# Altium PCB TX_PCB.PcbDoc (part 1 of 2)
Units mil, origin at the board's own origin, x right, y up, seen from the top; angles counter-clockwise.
Board outline 1955 x 2115 mil, 2 copper layers (Top Layer, Bottom Layer); 123 components, 95 nets, 485 pads, 266 vias.
Unrouted connection lines stored in the file: 109.
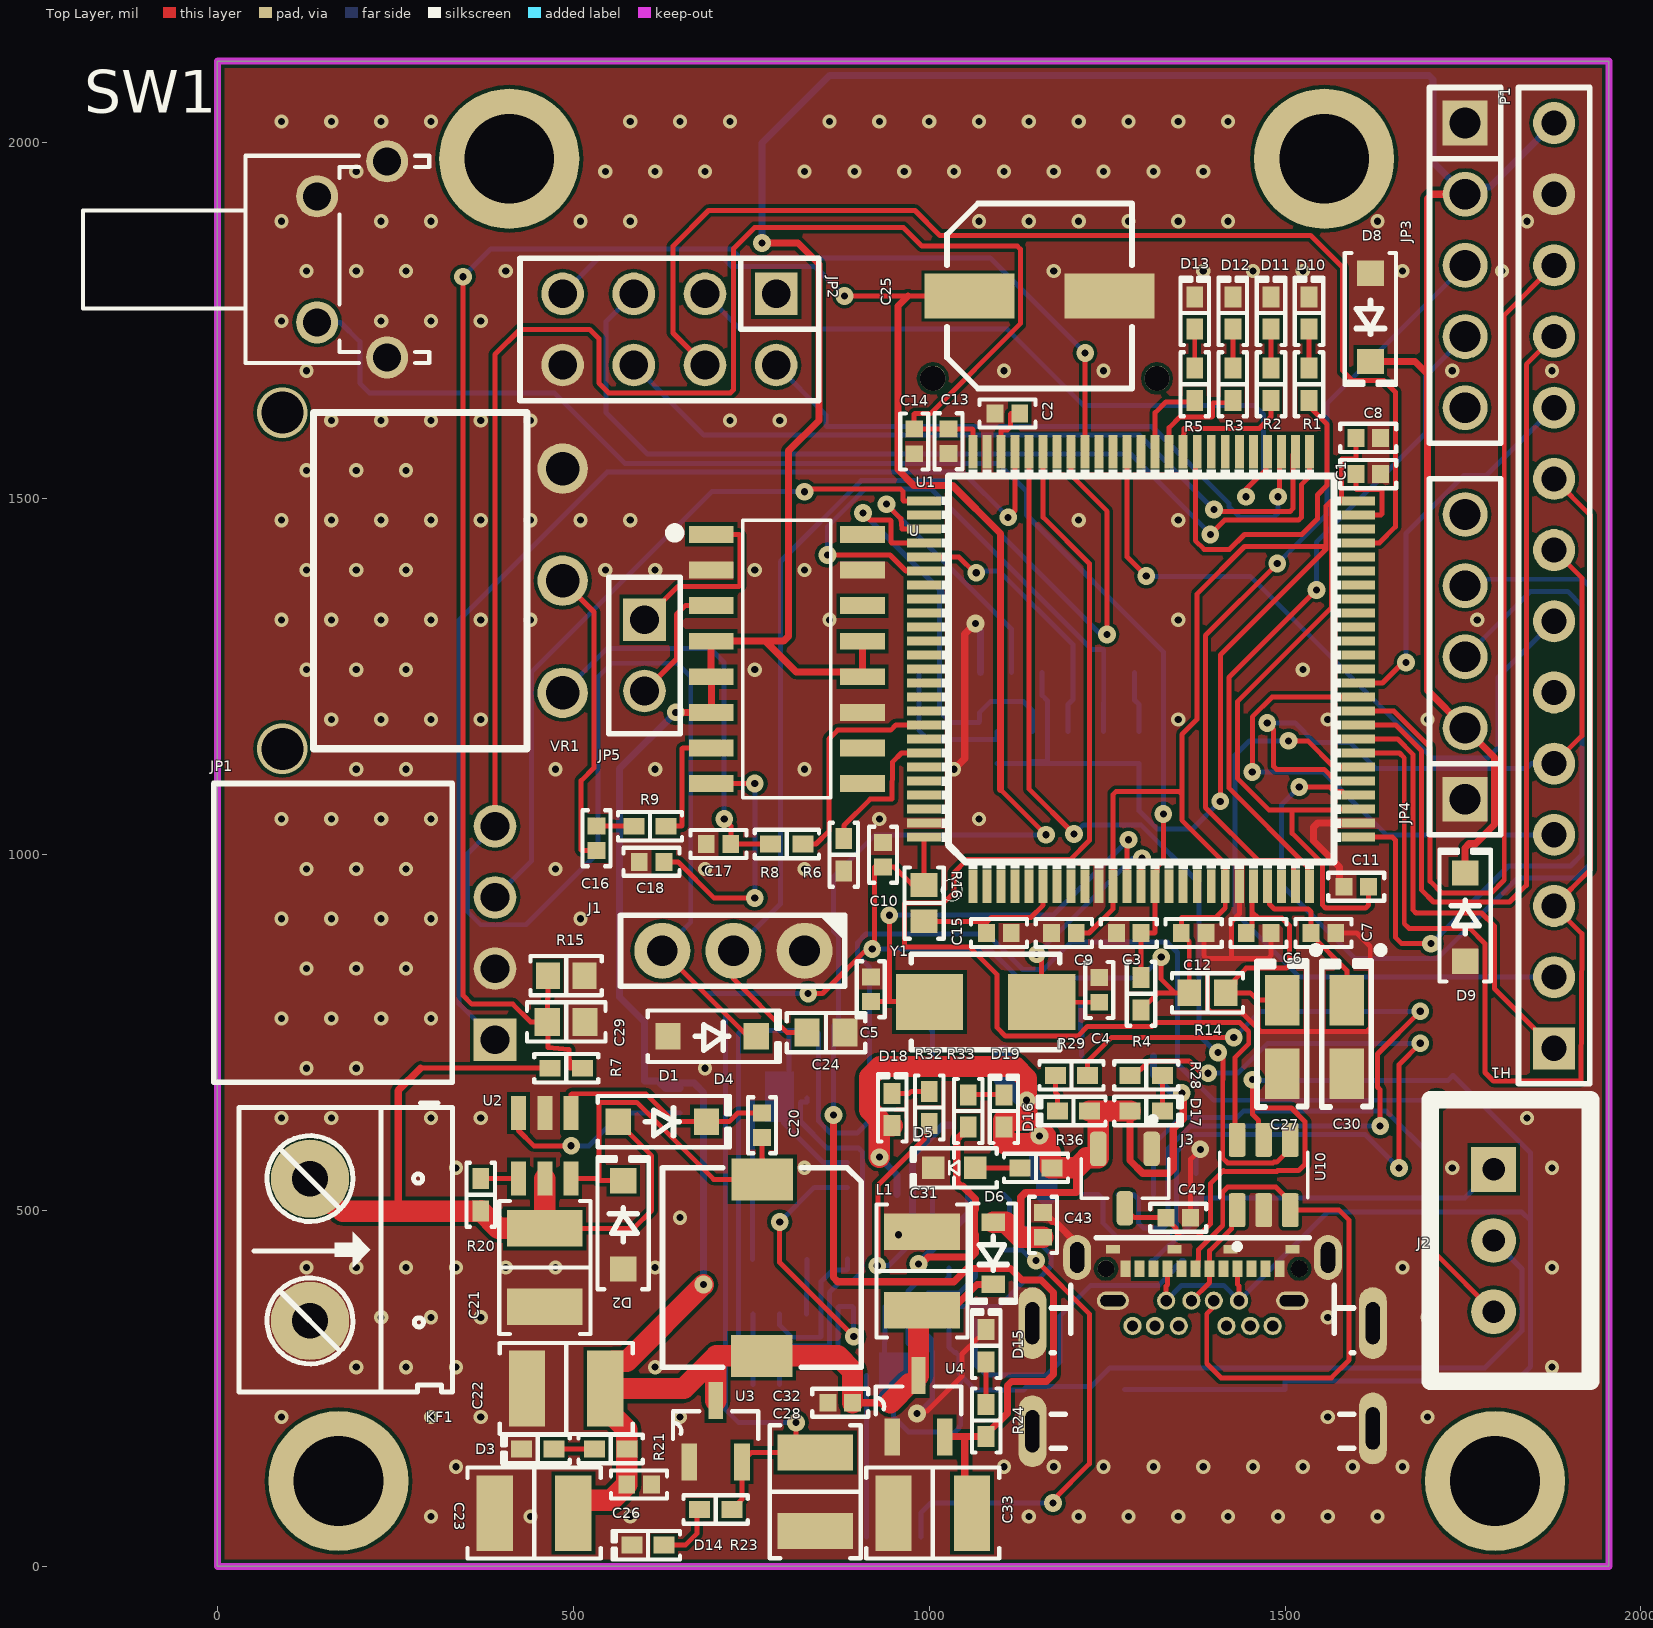
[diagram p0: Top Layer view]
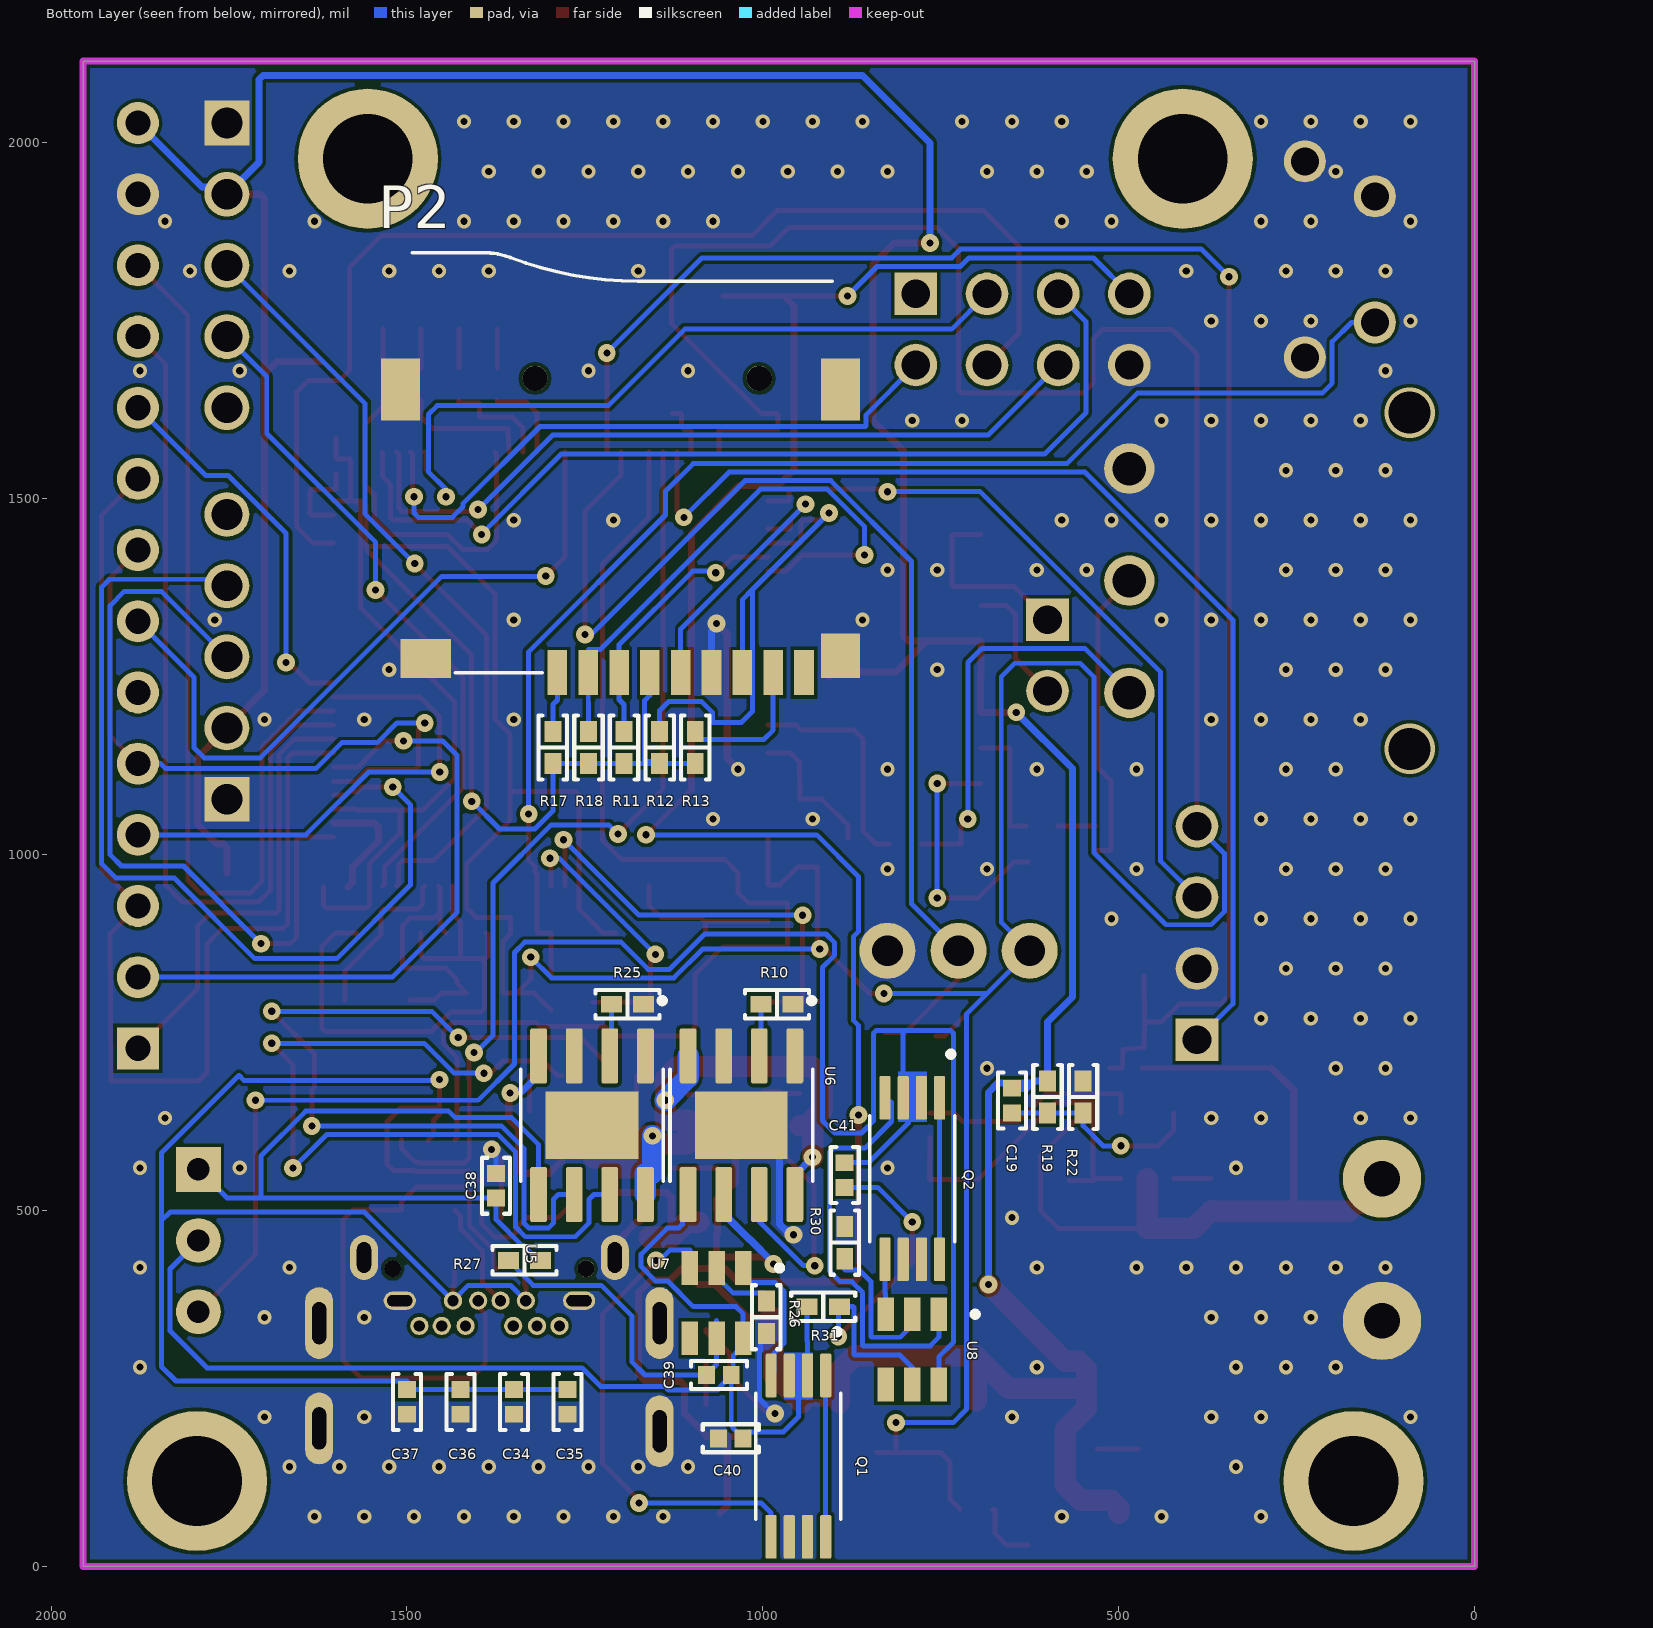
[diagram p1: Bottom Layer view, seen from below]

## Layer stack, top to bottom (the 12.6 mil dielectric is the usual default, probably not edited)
Top Solder: solder mask 0.4, Solder Resist, Dk 3.5
Top Layer: signal copper 1.4
Dielectric 1: dielectric 12.6, FR-4, Dk 4.8
Bottom Layer: signal copper 1.4
Bottom Solder: solder mask 0.4, Solder Resist, Dk 3.5

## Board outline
0,0 0,2115 1955,2115 1955,0

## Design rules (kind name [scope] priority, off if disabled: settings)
Clearance [All] p1: gap=5 ignorepadtopadclearanceinfootprint=FALSE
PolygonConnect PolygonConnect_5 [All vs IsNamedPolygon('GND_L02_P001')] p1: connectstyle=Direct reliefconductorwidth=10 reliefentries=4 polygonreliefangle="90 Angle" airgapwidth=10
PolygonConnect PolygonConnect_4 [All vs IsNamedPolygon('GND_L01_P000')] p2: connectstyle=Direct reliefconductorwidth=10 reliefentries=4 polygonreliefangle="90 Angle" airgapwidth=10
PolygonConnect PolygonConnect_3 [All vs IsNamedPolygon('GND_L01_P000')] p3: connectstyle=Direct reliefconductorwidth=10 reliefentries=4 polygonreliefangle="90 Angle" airgapwidth=10
PolygonConnect PolygonConnect_2 [All vs IsNamedPolygon('GND_L02_P001')] p4: connectstyle=Direct reliefconductorwidth=10 reliefentries=4 polygonreliefangle="90 Angle" airgapwidth=10
PolygonConnect PolygonConnect_1 [All vs IsNamedPolygon('GND_L01_P000')] p5: connectstyle=Direct reliefconductorwidth=10 reliefentries=4 polygonreliefangle="90 Angle" airgapwidth=10
PolygonConnect [All] p6: connectstyle=Relief reliefconductorwidth=10 reliefentries=4 polygonreliefangle="90 Angle" airgapwidth=10
RoutingVias [All] p1: holewidth=10 width=25 viastyle="Through Hole" minholewidth=10 minwidth=20 maxholewidth=28 maxwidth=50
SolderMaskExpansion [All] p1: expansion=4 istentingtop=FALSE
Width [All] p1: maxlimit=40 minlimit=7 preferedwidth=30 minimp=50.000000 maximp=50.000000 favimp=50.000000
30 further rules are at their usual default settings.

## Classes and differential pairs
component class USB_C: C34 C35 C36 C37 C38 C39 C40 C41 C42 C43 D5 D16 D17 D18 D19 H1 J2 J3 Q1 Q2 R10 R25 R26 R27 R28 R29 R30 R31 R32 R33 R36 U5 U6 U7 U8 U10
component class Audio: C16 C17 C18 JP5 P2 R8 R9 R11 R12 R13 R17 R18 U VR1
component class Power_2: C19 C20 C21 C22 C23 C26 C28 C31 C32 C33 D1 D2 D3 D14 D15 KF1 L1 R19 R20 R21 R22 R23 R24 U2 U3 U4
component class MAIN_TX: C1 C2 C3 C4 C5 C6 C7 C8 C9 C10 C11 C12 C13 C14 C15 C24 C25 C27 C29 C30 D4 D8 D9 D10 D11 D12 D13 J1 JP1 JP2 JP3 JP4 P1 R2 R3 R4 R5 R6 R7 R14 R15 R16 SW1 U1 Y1

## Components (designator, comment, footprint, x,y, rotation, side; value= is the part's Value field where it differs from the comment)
C1 "2.2 µF" "CAP 0402_1005" 1617,1534.69 r180 top
C2 "2.2 µF" "CAP 0402_1005" 1110,1620 r0 top
C3 "0.1 µF" "CAP 0402_1005" 1280.4,890 r0 top
C4 "20 pF" "CAP 0402_1005" 1239,810 r270 top
C5 "20 pF" "CAP 0402_1005" 918,811 r270 top
C6 "0.1 µF" "CAP 0402_1005" 1462.8,890 r180 top
C7 "0.1 µF" "CAP 0402_1005" 1554,890 r0 top
C8 "0.1 µF" "CAP 0402_1005" 1617,1585.69 r180 top
C9 "0.1 µF" "CAP 0402_1005" 1189.2,890 r0 top
C10 "0.1 µF" "CAP 0402_1005" 935,1000 r270 top
C11 "0.1 µF" "CAP 0402_1005" 1600,955 r0 top
C12 "0.1 µF" "CAP 0402_1005" 1371.6,890 r180 top
C13 "0.1 µF" "CAP 0402_1005" 1027,1581 r90 top
C14 "0.1 µF" "CAP 0402_1005" 979,1580.68 r90 top
C15 "1 µF" "CAP 0402_1005" 1098,890 r180 top
C16 "0.22 µF" "CAP 0402_1005" 532.64,1023 r90 top
C17 "0.1 µF" "CAP 0402_1005" 704,1015 r0 top
C18 "1 µF" "CAP 0402_1005" 610,990 r0 top
C19 "1000 pF" "CAP 0402_1005" 650,654.56 r90 bottom
C20 "0.1 µF" "CAP 0402_1005" 765,619.92 r90 top
C21 "10 µF" "CAP 1210_3225 - 1MM" 460,419.92 r90 top
C22 "22 µF" "CAP 1210_3225 - 1MM" 490,249.92 r0 top
C23 "10 µF" "CAP 1210_3225 - 1MM" 445,74.92 r0 top
C24 "0.1 µF" "CAP 0603_1608" 855,750 r180 top
C25 "220 µF" "CAP ALSMD 6.6MM H6.1MM" 1155,1785 r0 top
C26 "0.1µF" "CAP 0402_1005" 592.44,114.92 r180 top
C27 "1µF" "CAP POL 1206_3216" 1496,744 r270 top
C28 "10 µF" "CAP 1210_3225 - 1MM" 840,104.92 r90 top
C29 "0.1 µF" "CAP 0603_1608" 490,765 r180 top
C30 "1µF" "CAP POL 1206_3216" 1587,744 r270 top
C31 "10 µF" "CAP 1210_3225 - 1MM" 990,415 r270 top
C32 "0.1µF" "CAP 0402_1005" 875,229.92 r0 top
C33 "10 µF" "CAP 1210_3225 - 1MM" 1005,74.92 r0 top
C34 "0.1 µF" "CAP 0402_1005" 1349.74,231.1 r270 bottom
C35 "0.1 µF" "CAP 0402_1005" 1274.61,231.1 r270 bottom
C36 "0.1 µF" "CAP 0402_1005" 1424.87,231.1 r270 bottom
C37 "0.1 µF" "CAP 0402_1005" 1500,231.1 r270 bottom
C38 "10 µF" "CAP 0402_1005" 1375,534.92 r90 bottom
C39 "0.1 µF" "CAP 0402_1005" 1061.68,269 r180 bottom
C40 "10 µF" "CAP 0402_1005" 1045,180 r0 bottom
C41 "0.1 µF" "CAP 0402_1005" 885,549.92 r90 bottom
C42 "1 µF" "CAP 0402_1005" 1350,489.92 r180 top
C43 "1 µF" "CAP 0402_1005" 1160,479.92 r90 top
D1 "1N5819HW-7-F" SOD-123 625,624.92 r0 top
D2 "1N5819HW-7-F" SOD-123 570,479.92 r90 top
D3 "Green" "LED 0402_1005 GREEN" 450,164.92 r180 top
D4 "1N5819HW-7-F" SOD-123 695,745 r0 top
D5 "Blue" "LED 0603_1608 BLUE" 1035,559.92 r180 top
D6 "BAT60JFILM" SOD323 1090,439.92 r270 top
D8 "1N5819HW-7-F" SOD-123 1620,1755 r270 top
D9 "1N5819HW-7-F" SOD-123 1753,912.29 r90 top
D10 "Red" "LED 0402_1005 RED" 1533.72,1761 r90 top
D11 "Yellow" "LED 0402_1005 YELLOW" 1480.19,1761 r90 top
D12 "Green" "LED 0402_1005 GREEN" 1426.67,1761 r90 top
D13 "Blue" "LED 0402_1005 BLUE" 1373.14,1761 r90 top
D14 "Yellow" "LED 0402_1005 YELLOW" 605,29.92 r180 top
D15 "Red" "LED 0402_1005 RED" 1080,309.92 r90 top
D16 "Green" "LED 0402_1005 GREEN" 1202.64,639.92 r180 top
D17 "Red" "LED 0402_1005 RED" 1305,639.92 r0 top
D18 "Red" "LED 0402_1005 RED" 947.95,641.97 r90 top
D19 "Green" "LED 0402_1005 GREEN" 1105,639.92 r90 top
H1 "Header 3P 2.54 Duc Thang" XH2.54M-3 1793,557.92 r270 top
J1 "M20-7820342" "HARWIN M20-7820345" 725,865 r270 top
J2 "2129691-1" "TE USB-C 2129691-1" 1384.17,241.1 r180 top
J3 "MCP1700T-5002E/TT" SOT95P237X112-3N#1 1275,544.92 r270 top
JP1 "JP 1x4 2.54" "JP 1x4 CC" 390,890 r90 top
JP2 "JP 2x4 2.54" "JP 2x4 CT" 635,1738 r180 top
JP3 "JP 1x5 2.54" "JP 1x5 DT" 1753,2028 r270 top
JP4 "JP 1x5 2.54" "JP 1x5 DT" 1753,1078 r90 top
JP5 "JP 1x2 2.54" "JP 1x2 CT" 600,1330 r270 top
KF1 "CON 2 KF301" "Con 2 KF301 5.08" 130,544.92 r270 top
L1 "10µH" "TDK SLF7032" 765,419.92 r270 top
P1 "Header 14" HDR1X14 1878,728 r90 top
P2 "ST-TF-003A" SUNTECH_ST-TF-003A 1150,1465.72 r0 bottom
Q1 "FS8205A" SOP65P640X120-8N 950,154.92 r270 bottom
Q2 "FS8205A" SOP65P640X120-8N 790,544.92 r270 bottom
R1 "680 Ohms" "RES 0402_1005" 1533.72,1661 r90 top
R2 "680 Ohms" "RES 0402_1005" 1480.19,1661 r90 top
R3 "680 Ohms" "RES 0402_1005" 1426.67,1661 r90 top
R4 "100 kOhms" "RES 0402_1005" 1297.72,804.68 r270 top
R5 "680 Ohms" "RES 0402_1005" 1373.14,1661 r90 top
R6 "10 kOhms" "RES 0402_1005" 880,1000 r90 top
R7 "10 kOhms" "RES 0402_1005" 490,700 r180 top
R8 "4.7 kOhms" "RES 0402_1005" 800,1015 r0 top
R9 "10 kOhms" "RES 0402_1005" 607.64,1040 r0 top
R10 "1.2 kOhms" "RES 0402_1005" 980,789.92 r0 bottom
R11 "4.7 kOhms" "RES 0402_1005" 1195,1150.72 r270 bottom
R12 "4.7 kOhms" "RES 0402_1005" 1145,1150.72 r270 bottom
R13 "4.7 kOhms" "RES 0402_1005" 1095,1150.72 r270 bottom
R14 "47 Ohms" "RES 0603_1608" 1391,806 r0 top
R15 "20 kOhms" "RES 0603_1608" 490,830 r180 top
R16 "0 Ohms" "RES 0603_1608" 992.77,932 r270 top
R17 "4.7 kOhms" "RES 0402_1005" 1295,1150.72 r270 bottom
R18 "4.7 kOhms" "RES 0402_1005" 1245,1150.72 r270 bottom
R19 "52.3 kOhms" "RES 0402_1005" 600,659.56 r90 bottom
R20 "100 kOhms" "RES 0402_1005" 370,522.28 r270 top
R21 "1 kOhms" "RES 0402_1005" 552.48,164.92 r0 top
R22 "10 kOhms" "RES 0402_1005" 550,659.56 r270 bottom
R23 "680 Ohms" "RES 0402_1005" 700,79.92 r0 top
R24 "680 Ohms" "RES 0402_1005" 1080,204.92 r270 top
R25 "1.2 kOhms" "RES 0402_1005" 1190,789.92 r0 bottom
R26 "1 kOhms" "RES 0402_1005" 995,350 r270 bottom
R27 "110 Ohms" "RES 0402_1005" 1335,430 r180 bottom
R28 "1 kOhms" "RES 0402_1005" 1305,689.92 r0 top
R29 "1 kOhms" "RES 0402_1005" 1200,689.92 r0 top
R30 "1 kOhms" "RES 0402_1005" 885,454.92 r90 bottom
R31 "110 Ohms" "RES 0402_1005" 915,364.92 r0 bottom
R32 "1 kOhms" "RES 0402_1005" 1000,644.92 r90 top
R33 "1 kOhms" "RES 0402_1005" 1055,639.92 r270 top
R36 "1 kOhms" "RES 0402_1005" 1150,559.92 r0 top
SW1 "431256083716" 4312560837x6 105.55,1836.42 r270 top
U "PAM8403DR" SOIC127P605X150-16N 800,1275 r0 top
U1 "MCU-STM32F407VET6(LQFP100)" LQFP100-0.5-13.8X13.8MM 1297.89,1260.88 r90 top
U2 "LM2734YMK" SOT95P285X100-6N 460,590.92 r270 top
U3 "MCP1700T-3302E/TT" SOT95P237X112-3N#2 700,189.92 r90 top
U4 "MCP1700T-3302E/TT" SOT95P237X112-3N#2 985,224.92 r90 top
U5 "TP4056" SOP127P600X175-9N 1240,619.92 r270 bottom
U6 "TP4056" SOP127P600X175-9N 1030,619.92 r270 bottom
U7 "DW01A" SOT95P280X145-6N#1 1065,370 r270 bottom
U8 "DW01A" SOT95P280X145-6N#1 790,304.92 r270 bottom
U10 "USBLC6-2SC6" SOT95P280X145-6N#2 1470,549.92 r90 top
VR1 "VR 10Kohm" "VR 10kohm" 485,1148.78 r90 top
Y1 "8 MHz" "NDK NX5032GA" 1079.26,793 r180 top

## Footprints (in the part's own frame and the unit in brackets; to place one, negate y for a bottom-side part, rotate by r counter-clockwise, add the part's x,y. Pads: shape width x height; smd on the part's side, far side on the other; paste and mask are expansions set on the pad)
4312560837x6 [mm] "6x6mm right angle Tact Switch with ground terminal, THT version"
  round 1.5 hole 1: 1(-2.25,0.875) 2(2.25,0.875) G1(-3.5,3.375) G2(3.5,3.375)
  silkscreen extent -3.7,-7.47 3.7,4.87, body extent -4.2,-7.48 4.2,4.87, height 7.25
"CAP 0402_1005" [mm] "Chip Capacitor, 2-Leads, Body 1.02x0.51mm, IPC Medium Density"
  rect 0.6x0.64 smd: 1(-0.44,0) 2(0.44,0)
  silkscreen extent -1,-0.5 1,0.5, body extent -0.5,-0.26 0.5,0.26, height 0.52
"CAP 0603_1608" [mm] "Chip Capacitor, 2-Leads, Body 1.60x0.80mm, IPC Medium Density"
  rect 0.9x1 smd: 1(-0.675,0) 2(0.675,0)
  silkscreen extent -1.4,-0.7 1.4,0.7, body extent -0.8,-0.41 0.8,0.41, height 0.82
"CAP 1210_3225 - 1MM" [mm] "Chip Capacitor, 2-Leads, Body 3.20x2.50mm, IPC Medium Density"
  rect 1.3x2.7 smd: 1(-1.4,0) 2(1.4,0)
  silkscreen extent -2.38,-1.62 2.37,1.62, body extent -1.6,-1.25 1.6,1.25, height 1
"CAP ALSMD 6.6MM H6.1MM" [mm] "Aluminum Electrolytic Capacitor, Body 6.60x6.60x6.10mm, IPC Low Density"
  rect 3.2x1.6 smd: 1(-2.5,0) 2(2.5,0)
  silkscreen extent -3.3,-3.3 3.3,3.3, body extent -3.5,-3.3 3.5,3.3, height 6.1
"CAP POL 1206_3216" [mm] "Molded Capacitor, 2-Leads, Body 3.20x1.6mm, IPC Medium Density"
  rect 1.8x1.23 smd: 1(-1.31,0) 2(1.31,0)
  silkscreen extent -3.22,-0.9 2.5,1.33, body extent -1.72,-0.85 1.71,0.85, height 1.7
"Con 2 KF301 5.08" [mil]
  round 110 hole 50: 1(0,0) 2(200,0)
  silkscreen extent -106,-100 300,200, body extent -45,-97 255,190, height 335
"HARWIN M20-7820345" [mm] "2.54mm DIL PC TAIL PIN HEADER ASSEMBLY"
  round 2 hole 1.1: 1(0,2.54) 2(0,0) 3(0,-2.54)
  silkscreen extent -1.27,-4.03 1.27,4, body extent -1.25,-4.01 1.25,4.01, height 8.5
HDR1X14 [mm] "Connector; Header; 14 Position"
  rect 1.5x1.5 hole 0.9: 1(0,0)
  round 1.5 hole 0.9: 2(2.54,0) 3(5.08,0) 4(7.62,0) 5(10.16,0) 6(12.7,0) 7(15.24,0) 8(17.78,0) 9(20.32,0) 10(22.86,0) 11(25.4,0) 12(27.94,0) 13(30.48,0) 14(33.02,0)
  silkscreen extent -1.27,-1.27 34.29,1.27, body extent -1.27,-1.27 34.29,1.27, height 7
"JP 1x2 CT" [mm] "JP 1x2 CT"
  rect 1.52x1.52 hole 1.02: 1(0,0)
  round 1.52 hole 1.02: 2(2.54,0)
  silkscreen extent -1.52,-1.27 4.06,1.27, body extent -1.52,-1.25 4.06,1.25, height 8.51
"JP 1x4 CC" [mm] "4 pins, 1 row, straight, gold plating"
  rect 1.52x1.52 hole 1.02: 1(-3.81,0)
  round 1.52 hole 1.02: 2(-1.27,0) 3(1.27,0) 4(3.81,0)
  silkscreen extent -5.33,1.52 5.33,10.03, body extent -5.33,-0.25 5.33,10.05, height 2.51
"JP 1x5 DT" [mm] "5 pins, 1 row, straight, gold plating"
  rect 1.6x1.6 hole 1.1: 1(0,0)
  round 1.6 hole 1.1: 2(2.54,0) 3(5.08,0) 4(7.62,0) 5(10.16,0)
  silkscreen extent -1.27,-1.27 11.43,1.27, body extent -1.27,-1.27 11.43,1.27, height 8.54
"JP 2x4 CT" [mm] "8 pins, dual row, straight, gold plating"
  rect 1.52x1.52 hole 1.02: 1(-3.81,-1.27)
  round 1.52 hole 1.02: 2(-1.27,-1.27) 3(1.27,-1.27) 4(3.81,-1.27) 5(3.81,1.27) 6(1.27,1.27) 7(-1.27,1.27) 8(-3.81,1.27)
  silkscreen extent -5.33,-2.54 5.33,2.54, body extent -5.33,-2.54 5.33,2.54, height 8.51
"LED 0402_1005 BLUE" [mm] "Chip Diode, 2-Leads, Body 1.00x0.50mm, IPC Medium Density"
  rect 0.75x0.6 smd: 1(-0.575,0) 2(0.575,0)
  silkscreen extent -1.14,-0.51 1.27,0.51, body extent -0.5,-0.25 0.5,0.25, height 0.21
"LED 0402_1005 GREEN" [mm] "Chip Diode, 2-Leads, Body 1.00x0.50mm, IPC Medium Density"
  rect 0.75x0.6 smd: 1(-0.575,0) 2(0.575,0)
  silkscreen extent -1.14,-0.51 1.27,0.51, body extent -0.5,-0.25 0.5,0.25, height 0.21
"LED 0402_1005 RED" [mm] "Chip Diode, 2-Leads, Body 1.00x0.50mm, IPC Medium Density"
  rect 0.75x0.6 smd: 1(-0.575,0) 2(0.575,0)
  silkscreen extent -1.14,-0.51 1.27,0.51, body extent -0.5,-0.25 0.5,0.25, height 0.21
"LED 0402_1005 YELLOW" [mm] "Chip Diode, 2-Leads, Body 1.00x0.50mm, IPC Medium Density"
  rect 0.75x0.6 smd: 1(-0.575,0) 2(0.575,0)
  silkscreen extent -1.14,-0.51 1.27,0.51, body extent -0.5,-0.25 0.5,0.25, height 0.21
"LED 0603_1608 BLUE" [mm] "Chip Diode, 2-Leads, Body 1.60x0.80mm, IPC Medium Density"
  rect 0.8x0.8 smd: 1(-0.75,0) 2(0.75,0)
  silkscreen extent -1.52,-0.7 1.52,0.7, body extent -0.8,-0.4 0.8,0.4, height 0.53
LQFP100-0.5-13.8X13.8MM [mm]
  rect 1.2x0.32 smd: 1(-7.75,6) 2(-7.75,5.5) 3(-7.75,5) 4(-7.75,4.5) 5(-7.75,4) 6(-7.75,3.5) 7(-7.75,3) 8(-7.75,2.5) 9(-7.75,2) 10(-7.75,1.5) 11(-7.75,1) 12(-7.75,0.5) 13(-7.75,0) 14(-7.75,-0.5) 15(-7.75,-1) 16(-7.75,-1.5) 17(-7.75,-2) 18(-7.75,-2.5) 19(-7.75,-3) 20(-7.75,-3.5) 21(-7.75,-4) 22(-7.75,-4.5) 23(-7.75,-5) 24(-7.75,-5.5) 25(-7.75,-6) 51(7.75,-6) 52(7.75,-5.5) 53(7.75,-5) 54(7.75,-4.5) 55(7.75,-4) 56(7.75,-3.5) 57(7.75,-3) 58(7.75,-2.5) 59(7.75,-2) 60(7.75,-1.5) 61(7.75,-1) 62(7.75,-0.5) 63(7.75,0) 64(7.75,0.5) 65(7.75,1) 66(7.75,1.5) 67(7.75,2) 68(7.75,2.5) 69(7.75,3) 70(7.75,3.5) 71(7.75,4) 72(7.75,4.5) 73(7.75,5) 74(7.75,5.5) 75(7.75,6)
  rect 0.32x1.2 smd: 26(-6,-7.75) 27(-5.5,-7.75) 28(-5,-7.75) 29(-4.5,-7.75) 30(-4,-7.75) 31(-3.5,-7.75) 32(-3,-7.75) 33(-2.5,-7.75) 34(-2,-7.75) 35(-1.5,-7.75) 36(-1,-7.75) 37(-0.5,-7.75) 38(0,-7.75) 39(0.5,-7.75) 40(1,-7.75) 41(1.5,-7.75) 42(2,-7.75) 43(2.5,-7.75) 44(3,-7.75) 45(3.5,-7.75) 46(4,-7.75) 47(4.5,-7.75) 48(5,-7.75) 49(5.5,-7.75) 50(6,-7.75) 76(6,7.75) 77(5.5,7.75) 78(5,7.75) 79(4.5,7.75) 80(4,7.75) 81(3.5,7.75) 82(3,7.75) 83(2.5,7.75) 84(2,7.75) 85(1.5,7.75) 86(1,7.75) 87(0.5,7.75) 88(0,7.75) 89(-0.5,7.75) 90(-1,7.75) 91(-1.5,7.75) 92(-2,7.75) 93(-2.5,7.75) 94(-3,7.75) 95(-3.5,7.75) 96(-4,7.75) 97(-4.5,7.75) 98(-5,7.75) 99(-5.5,7.75) 100(-6,7.75)
  silkscreen extent -8.27,-7.13 7.11,7.15, body extent -8,-8 8,8, height 1.6
"NDK NX5032GA" [mm] "Crystal, 2-Leads, Body 5.00x3.20mm, IPC Medium Density"
  rect 2.4x2 smd: 1(-2,0) 2(2,0)
  silkscreen extent -2.65,-1.7 2.65,1.7, body extent -2.5,-1.6 2.5,1.6, height 1.2
"RES 0402_1005" [mm] "Chip Resistor, 2-Leads, Body 1.0x0.5mm, IPC Medium Density"
  rect 0.75x0.6 smd: 1(-0.575,0) 2(0.575,0)
  silkscreen extent -1.14,-0.51 1.14,0.51, body extent -0.5,-0.25 0.5,0.25, height 0.35
"RES 0603_1608" [mm] "Chip Resistor, 2-Leads, Body 1.60x0.80mm, IPC Medium Density"
  rect 0.85x0.95 smd: 1(-0.65,0) 2(0.65,0)
  silkscreen extent -1.27,-0.7 1.27,0.7, body extent -0.8,-0.4 0.8,0.4, height 0.45
SOD323 [mm] "SOD, 2-Leads, Body 1.25x2.50mm, IPC Medium Density"
  rect 0.625x0.83 smd: 1(-1.113,0) 2(1.113,0)
  silkscreen extent -1.78,-0.8 1.78,0.8, body extent -1.36,-0.62 1.36,0.62, height 1.05
SOD-123 [mm] "SOD, 2-Leads, Body 1.55x3.70mm, IPC Medium Density"
  rect 0.9x0.95 smd: 1(-1.575,0) 2(1.575,0)
  silkscreen extent -2.3,-0.92 2.41,0.92, body extent -1.86,-0.78 1.86,0.77, height 1.35
SOIC127P605X150-16N [mm]
  rect 1.6x0.6 smd: 1(-2.7,4.445) 2(-2.7,3.175) 3(-2.7,1.905) 4(-2.7,0.635) 5(-2.7,-0.635) 6(-2.7,-1.905) 7(-2.7,-3.175) 8(-2.7,-4.445) 9(2.7,-4.445) 10(2.7,-3.175) 11(2.7,-1.905) 12(2.7,-0.635) 13(2.7,0.635) 14(2.7,1.905) 15(2.7,3.175) 16(2.7,4.445)
  silkscreen extent -4.14,-4.95 1.58,4.95
SOP65P640X120-8N [mm]
  rrect25% 1.56x0.4 smd: 1(-2.88,0.975) 2(-2.88,0.325) 3(-2.88,-0.325) 4(-2.88,-0.975) 5(2.88,-0.975) 6(2.88,-0.325) 7(2.88,0.325) 8(2.88,0.975)
  silkscreen extent -4.54,-1.52 2.25,1.52, body extent -3.2,-1.47 3.2,1.46, height 1.2
SOP127P600X175-9N [mm]
  rrect25% 1.97x0.6 smd: 1(-2.475,1.905) 2(-2.475,0.635) 3(-2.475,-0.635) 4(-2.475,-1.905) 5(2.475,-1.905) 6(2.475,-0.635) 7(2.475,0.635) 8(2.475,1.905)
  rect 2.413x3.302 smd paste-3: 9(0,0)
  silkscreen extent -4.54,-2.55 2,2.6, body extent -3,-2.45 3,2.45, height 1.75
SOT95P237X112-3N#1 [mm]
  rrect50% 1.23x0.59 smd: 1(-1.06,0.95) 2(-1.06,-0.95) 3(1.06,0)
  silkscreen extent -2.2,-1.56 0.7,1.56
SOT95P237X112-3N#2 [mm]
  rect 1.321x0.559 smd: 1(-1.092,0.94) 2(-1.092,-0.94)
  rect 1.321x0.508 smd: 3(1.092,0)
  silkscreen extent -0.28,-1.52 0.71,1.53
SOT95P280X145-6N#1 [mm]
  rect 1.21x0.59 smd: 1(-1.255,0.95) 2(-1.255,0) 3(-1.255,-0.95) 4(1.255,-0.95) 5(1.255,0) 6(1.255,0.95)
  silkscreen extent -1.35,2.14 -1.16,2.34, body extent -1.4,-1.45 1.4,1.45, height 1.45
SOT95P280X145-6N#2 [mm]
  rrect25% 1.21x0.59 smd: 1(-1.255,0.95) 2(-1.255,0) 3(-1.255,-0.95) 4(1.255,-0.95) 5(1.255,0) 6(1.255,0.95)
  silkscreen extent -2.65,-1.56 0.81,1.56, body extent -1.53,-1.46 1.27,1.46, height 1.4
SOT95P285X100-6N [mil]
  rect 48x21 smd: 1(-46,37) 2(-46,0) 3(-46,-37) 4(46,-37) 5(46,0) 6(46,37)
SUNTECH_ST-TF-003A [mm]
  rect 0.7x1.6 smd: 1(3.52,5.33) 2(2.42,5.33) 3(1.32,5.33) 4(0.22,5.33) 5(-0.88,5.33) 6(-1.98,5.33) 7(-3.08,5.33) 8(-4.18,5.33) 9(-5.28,5.33)
  rect 1.4x1.6 smd: G1(-6.58,4.73)
  rect 1.4x2.2 smd: G2(-6.58,-4.77) G3(9.12,-4.77)
  rect 1.8x1.4 smd: G4(8.22,4.83)
  round 0.9 hole 0.9 unplated: ""(-3.68,-5.17) ""(4.32,-5.17)
  silkscreen extent -6.29,-9.66 8.7,5.33, body extent -6.78,-9.28 9.32,5.72, height 1.9
"TDK SLF7032" [mm] "Power Inductor, 2-Leads, TDK, SLF7032T-221MR29-2PF"
  rect 1.5x2.2 smd: 1(-3.15,0.013) 2(3.15,-0.012)
  silkscreen extent -3.56,-3.55 3.56,3.55, body extent -3.56,-3.56 3.56,3.54, height 3.39
"TE USB-C 2129691-1" [mm]
  rect 0.35x0.6 smd: A1(2.75,-4.5) A2(2.25,-4.5) A3(1.75,-4.5) A4(1.25,-4.5) A5(0.75,-4.5) A6(0.25,-4.5) A7(-0.25,-4.5) A8(-0.75,-4.5) A9(-1.25,-4.5) A10(-1.75,-4.5) A11(-2.25,-4.5) A12(-2.75,-4.5)
  oval 1.15x0.65 hole 0.4 slot 0.9 at 0 deg: B1(-3.2,-3.36) B12(3.2,-3.36)
  round 0.65 hole 0.4: B2(-2.5,-2.46) B3(-1.7,-2.46) B4(-1.3,-3.36) B5(-0.85,-2.46) B6(-0.4,-3.36) B7(0.4,-3.36) B8(0.85,-2.46) B9(1.3,-3.36) B10(1.7,-2.46) B11(2.5,-2.46)
  round 0.6 hole 0.6 unplated mask+0.102: M(-3.45,-4.5) M(3.45,-4.5)
  oval 1x2.56 hole 0.5 slot 1.5 at 90 deg: S(-6.075,-2.56) S(-6.075,1.2) S(6.075,-2.56) S(6.075,1.3)
  oval 1x1.6 hole 0.5 slot 1.1 at 90 deg: S(-4.475,-4.9) S(4.475,-4.9)
  rect 0.5x0.3 smd: S(-3.2,-5.19) S(-1,-5.19) S(1,-5.19) S(3.2,-5.19)
  silkscreen extent -5.4,-5.6 5.4,1.9, body extent -6.17,-5.3 6.18,5.4, height 3.27
"VR 10kohm" [mm]
  round 1.8 hole 1.2: 0(6,0) 1(2,0) 2(10,0)
  silkscreen extent 0,1.27 12,8.89
XH2.54M-3 [mm]
  rect 1.6x1.6 hole 0.8: 1(0,0)
  round 1.6 hole 0.8: 2(2.54,0) 3(5.08,0)
  silkscreen extent -2.48,-2.26 7.56,3.46, body extent -2.48,-2.26 7.56,3.48, height 6.91

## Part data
C1 C2: library part GRT155C81A225KE13D, "CAP CER 2.2UF 10V X6S 0402", Device Package="0402 (1005 Metric)", Manufacturer="Murata Electronics", Operating Temperature="-55°C ~ 105°C", Ratings=AEC-Q200, Supplier Part Number 1=490-12239-1-ND, Temperature Coefficient=X6S, Tolerance=±10%, Voltage - Rated=10V
C3 C6 C7 C8 C9 C10 C11 C12 C13 C14 C20: library part KGM05AR51A104KN, "CAP CER 0.1UF 10V X5R 0402", Device Package="0402 (1005 Metric)", Manufacturer="KYOCERA AVX", Operating Temperature="-55°C ~ 85°C", Supplier Part Number 1=478-KGM05AR51A104KNCT-ND, Temperature Coefficient=X5R, Tolerance=±10%, Voltage - Rated=10V
C4 C5: library part C0402C200K8GAC7867, "CAP CER 20PF 10V NP0 0402", Device Package="0402 (1005 Metric)", Manufacturer=KEMET, Operating Temperature="-55°C ~ 125°C", Supplier Part Number 1=399-14429-1-ND, Temperature Coefficient="C0G, NP0", Tolerance=±10%, Voltage - Rated=10V
C15: library part GRM155C71A105KE11D, "CAP CER 1UF 10V X7S 0402", Device Package="0402 (1005 Metric)", Manufacturer="Murata Electronics", Operating Temperature="-55°C ~ 125°C", Supplier Part Number 1=490-14457-1-ND, Temperature Coefficient=X7S, Tolerance=±10%, Voltage - Rated=10V
C16: library part 0402X224K100CT, "CAP CER 0.22UF 10V X5R 0402", Device Package="0402 (1005 Metric)", Manufacturer="Walsin Technology Corporation", Operating Temperature="-55°C ~ 85°C", Supplier Part Number 1=1292-1370-1-ND, Temperature Coefficient=X5R, Tolerance=±10%, Voltage - Rated=10V
C17: library part CGA2B2X5R1A104M050BA, "CAP CER 0.1UF 10V X5R 0402", Device Package="0402 (1005 Metric)", Manufacturer="TDK Corporation", Operating Temperature="-55°C ~ 85°C", Ratings=AEC-Q200, Supplier Part Number 1=445-12157-1-ND, Temperature Coefficient=X5R, Tolerance=±20%, Voltage - Rated=10V
C18: library part C0402C105K8PAC7867, "CAP CER 1UF 10V X5R 0402", Device Package="0402 (1005 Metric)", Manufacturer=KEMET, Operating Temperature="-55°C ~ 85°C", Supplier Part Number 1=399-C0402C105K8PAC7867CT-ND, Temperature Coefficient=X5R, Tolerance=±10%, Voltage - Rated=10V
C19: library part LMF105B7102MVHF, "CAP CER 1000PF 10V X7R 0402", Device Package="0402 (1005 Metric)", Manufacturer="Taiyo Yuden", Operating Temperature="-55°C ~ 125°C", Ratings=AEC-Q200, Supplier Part Number 1=587-LMF105B7102MVHFCT-ND, Temperature Coefficient=X7R, Tolerance=±20%, Voltage - Rated=10V
C21 C23 C28 C31 C33: library part CGA6P3X8R1C106M250AB, "CAP CER 10UF 16V X8R 1210", Device Package="1210 (3225 Metric)", Manufacturer="TDK Corporation", Operating Temperature="-55°C ~ 150°C", Ratings=AEC-Q200, Supplier Part Number 1=445-13057-1-ND, Temperature Coefficient=X8R, Tolerance=±20%, Voltage - Rated=16V
C22: library part C1210C226K4RAC7800, "CAP CER 22UF 16V X7R 1210", Device Package="1210 (3225 Metric)", Manufacturer=KEMET, Operating Temperature="-55°C ~ 125°C", Supplier Part Number 1=399-11662-1-ND, Temperature Coefficient=X7R, Tolerance=±10%, Voltage - Rated=16V
C24 C29: library part VJ0603Y104KXQCW1BC, "CAP CER 0.1UF 10V X7R 0603", Device Package="0603 (1608 Metric)", Manufacturer="Vishay Vitramon", Operating Temperature="-55°C ~ 125°C", Supplier Part Number 1=720-1689-1-ND, Temperature Coefficient=X7R, Tolerance=±10%, Voltage - Rated=10V
C25: library part UCM1A221MCL1GS, "CAP ALUM 220UF 20% 10V SMD", Device Package="Radial, Can - SMD", Lifetime @ Temp.="2000 Hrs @ 105°C", Manufacturer=Nichicon, Operating Temperature="-55°C ~ 105°C", Ratings=AEC-Q200, Ripple Current @ High Frequency="300 mA @ 100 kHz", Ripple Current @ Low Frequency="150 mA @ 120 Hz", Supplier Part Number 1=493-17470-1-ND, Tolerance=±20%, Voltage - Rated="10 V"
C26 C32: library part 0402ZC104KAT2A, "CAP CER 0.1UF 10V X7R 0402", Device Package="0402 (1005 Metric)", Manufacturer="AVX Corporation", Operating Temperature="-55°C ~ 125°C", Supplier Part Number 1=478-7891-1-ND, Temperature Coefficient=X7R, Tolerance=±10%, Voltage - Rated=10V
C27 C30: library part TAJA105K016RNJ, "CAP TANT 1UF 10% 16V 1206", Device Package="1206 (3216 Metric)", ESR (Equivalent Series Resistance)=11Ohm, Manufacturer="AVX Corporation", Manufacturer Size Code=A, Operating Temperature="-55°C ~ 125°C", Supplier Part Number 1=478-1649-1-ND, Tolerance=±10%, Voltage - Rated=16V
C34 C35 C36 C37 C39: library part KGM05AR71A104KH, "CAP CER 0.1UF 10V X7R 0402", Device Package="0402 (1005 Metric)", Manufacturer="KYOCERA AVX", Operating Temperature="-55°C ~ 125°C", Supplier Part Number 1=478-KGM05AR71A104KHCT-ND, Temperature Coefficient=X7R, Tolerance=±10%, Voltage - Rated=10V
C38 C40: library part CL05A106MP8NUB8, "CAP CER 10UF 10V X5R 0402", Device Package="0402 (1005 Metric)", Manufacturer="Samsung Electro-Mechanics", Operating Temperature="-55°C ~ 85°C", Supplier Part Number 1=1276-6830-1-ND, Temperature Coefficient=X5R, Tolerance=±20%, Voltage - Rated=10V
C41: library part KGM05AV51A104ZH, "CAP CER 0.1UF 10V Y5V 0402", Device Package="0402 (1005 Metric)", Manufacturer="KYOCERA AVX", Operating Temperature="-30°C ~ 85°C", Supplier Part Number 1=478-KGM05AV51A104ZHCT-ND, Temperature Coefficient="Y5V (F)", Tolerance="-20%, +80%", Voltage - Rated=10V
C42 C43: library part KGM05AR51A105KH, "CAP CER 1UF 10V X5R 0402", Device Package="0402 (1005 Metric)", Manufacturer="KYOCERA AVX", Operating Temperature="-55°C ~ 85°C", Supplier Part Number 1=478-CM05X5R105K10AHCT-ND, Temperature Coefficient=X5R, Tolerance=±10%, Voltage - Rated=10V
D1 D2 D4 D8 D9: "DIODE SCHOTTKY 40V 1A SOD123", Capacitance @ Vr, F="60pF @ 4V, 1MHz", Current - Average Rectified (Io)=1A, Current - Reverse Leakage @ Vr="1 mA @ 40 V", Manufacturer="Diodes Incorporated", Operating Temperature - Junction="-65°C ~ 125°C", Package / Case=SOD-123, Supplier Part Number 1=1N5819HW-FDICT-ND, Voltage - DC Reverse (Vr) (Max)="40 V", Voltage - Forward (Vf) (Max) @ If="450 mV @ 1 A"
D3: library part QBLP595-AG15-2897, "LED GREEN CLEAR 0402 SMD", Current - Test=5mA, Device Package="0402 (1005 Metric)", Lens Color=Colorless, Manufacturer="QT Brightek (QTB)", Millicandela Rating=16.5mcd, Supplier Device Package=0402, Supplier Part Number 1=1516-QBLP595-AG15-2897CT-ND, Voltage - Forward (Vf) (Typ)=1.9V
D5: library part 150060BS75000, "LED BLUE CLEAR 0603 SMD", Current - Test=20mA, Device Package="0603 (1608 Metric)", Lens Color=Colorless, Manufacturer="Würth Elektronik", Millicandela Rating=145mcd, Supplier Device Package=0603, Supplier Part Number 1=732-4966-1-ND, Voltage - Forward (Vf) (Typ)=3.2V
D6: "DIODE SCHOTTKY 10V 3A SOD323", Current - Average Rectified (Io)=3A, Current - Reverse Leakage @ Vr="6 µA @ 10 V", Manufacturer=STMicroelectronics, Operating Temperature - Junction="150°C (Max)", Package / Case="SC-76, SOD-323", Supplier Device Package=SOD-323, Supplier Part Number 1=497-3707-1-ND, Voltage - DC Reverse (Vr) (Max)="10 V", Voltage - Forward (Vf) (Max) @ If="580 mV @ 1 A"
D10: library part SM0402RC, "LED RED CLEAR 0402 SMD", Current - Test=20mA, Device Package="0402 (1005 Metric)", Lens Color=Colorless, Manufacturer="Bivar Inc.", Millicandela Rating=90mcd, Supplier Device Package=0402, Supplier Part Number 1=492-2208-1-ND, Voltage - Forward (Vf) (Typ)=2.1V
D11: library part IN-S42ATY, "LED YELLOW CLEAR 0402 SMD", Current - Test=20mA, Device Package="0402 (1005 Metric)", Lens Color=Clear, Manufacturer=Inolux, Millicandela Rating=145mcd, Supplier Device Package=0402, Supplier Part Number 1=1830-1059-1-ND, Voltage - Forward (Vf) (Typ)=1.9V
D12: library part APG1005ZGC-5MAV, "LED GREEN CLEAR 0402 SMD", Current - Test=5mA, Device Package="0402 (1005 Metric)", Lens Color=Colorless, Manufacturer=Kingbright, Millicandela Rating=280mcd, Supplier Device Package=0402, Supplier Part Number 1=754-APG1005ZGC-5MAVCT-ND, Voltage - Forward (Vf) (Typ)=2.85V
D13: library part XZBBR68W5MAV-3, "LED BLUE CLEAR 0402 SMD", Current - Test=5mA, Device Package="0402 (1005 Metric)", Lens Color=Colorless, Manufacturer=SunLED, Millicandela Rating=27mcd, Supplier Device Package=0402, Supplier Part Number 1=1497-1388-1-ND, Voltage - Forward (Vf) (Typ)=2.9V
D14: library part IN-S42BT5Y, "LED YELLOW CLEAR 0402 SMD", Current - Test=5mA, Device Package="0402 (1005 Metric)", Lens Color=0.50mm, Manufacturer=Inolux, Millicandela Rating=23mcd, Supplier Device Package=0402, Supplier Part Number 1=1830-IN-S42BT5YCT-ND, Voltage - Forward (Vf) (Typ)=2V
D15: library part QBLP595-R5, "LED RED CLEAR 0402 SMD", Current - Test=5mA, Device Package="0402 (1005 Metric)", Lens Color=Colorless, Manufacturer="QT Brightek (QTB)", Millicandela Rating=31.5mcd, Supplier Device Package=0402, Supplier Part Number 1=1516-QBLP595-R5CT-ND, Voltage - Forward (Vf) (Typ)=1.85V
D16 D19: library part 150040GS73240, "LED GREEN CLEAR 0402 SMD", Current - Test=20mA, Device Package="0402 (1005 Metric)", Lens Color=Colorless, Manufacturer="Würth Elektronik", Millicandela Rating=800mcd, Supplier Part Number 1=732-11990-1-ND, Voltage - Forward (Vf) (Typ)=3.2V
D17 D18: library part 150040SS73220, "LED RED CLEAR 0402 SMD", Current - Test=20mA, Device Package="0402 (1005 Metric)", Lens Color=Colorless, Manufacturer="Würth Elektronik", Millicandela Rating=90mcd, Supplier Device Package=0402, Supplier Part Number 1=732-13421-1-ND, Voltage - Forward (Vf) (Typ)=2V
H1 KF1: "Cắm"
J1: "CONN RCPT 3POS 0.1 GOLD PCB", Current Rating (Amps)=3A, Insulation Color=Black, Manufacturer="Harwin Inc.", Material Flammability Rating="UL94 V-0", Operating Temperature="-40°C ~ 105°C", Supplier Part Number 1=952-1783-ND
J2: "CONN RCPT USB3.1 TYPEC 24POS SMD", Current Rating (Amps)="0.25A, 1.25A, 5A", Manufacturer="TE Connectivity AMP Connectors", Operating Temperature="-30°C ~ 85°C", Supplier Part Number 1=A122008TR-ND, Voltage - Rated=30V
J3: Package=None
JP1: library part "JP 1x4 2.54 Cai Cong", "Cắm"
JP2: library part "JP 2x4 2.54 Cai Thang", "Cắm"
JP3 JP4: library part "JP 1x5 2.54 Duc Thang", "Cắm"
JP5: library part "JP 1x2 2.54 Cai Thang", "Cắm"
L1: library part SLF7032T-100M1R4-2PF, "FIXED IND 10UH 1.4A 63.6 MOHM", Current Rating (Amps)=1.4A, DC Resistance (DCR)="63.6mOhm Max", Device Package=Nonstandard, Inductance Frequency - Test=100kHz, Manufacturer="TDK Corporation", Operating Temperature="-40°C ~ 105°C", Supplier Part Number 1=445-1998-1-ND, Tolerance=±20%
P1: "Header, 14-Pin"
P2: "Micro SD Card Socket", Package=None
Q1 Q2: "N/A", Package=Package
R1 R2 R3 R5 R23 R24: library part RC0402FR-07680RL, "RES 680 OHM 1% 1/16W 0402", Device Package="0402 (1005 Metric)", Manufacturer=Yageo, Operating Temperature="-55°C ~ 155°C", Power (Watts)="0.063W, 1/16W", Supplier Device Package=0402, Supplier Part Number 1=311-680LRCT-ND, Temperature Coefficient=±100ppm/°C, Tolerance=±1%
R4: library part MCS04020D1003BE100, "RES SMD 100K OHM 0.1% 1/16W 0402", Device Package="0402 (1005 Metric)", Manufacturer="Vishay Beyschlag", Operating Temperature="-55°C ~ 125°C", Power (Watts)="0.063W, 1/16W", Supplier Device Package=0402, Supplier Part Number 1=749-1594-1-ND, Temperature Coefficient=±25ppm/°C, Tolerance=±0.1%
R6 R7: library part RP73PF1E10KBTD, "RES 10K OHM 0.1% 1/10W 0402", Device Package="0402 (1005 Metric)", Manufacturer="TE Connectivity Passive Product", Operating Temperature="-55°C ~ 155°C", Power (Watts)="0.1W, 1/10W", Supplier Device Package=0402, Supplier Part Number 1=A127415CT-ND, Temperature Coefficient=±25ppm/°C, Tolerance=±0.1%
R8 R11 R12 R13 R17 R18: library part RK73H1ERTTP4701F, "RES 4.7K OHM 1% 1/10W 0402", Device Package="0402 (1005 Metric)", Manufacturer="KOA Speer Electronics, Inc.", Operating Temperature="-55°C ~ 155°C", Power (Watts)="0.1W, 1/10W", Ratings=AEC-Q200, Supplier Device Package=0402, Supplier Part Number 1=2019-RK73H1ERTTP4701FCT-ND, Temperature Coefficient=±100ppm/°C, Tolerance=±1%
R9 R22: library part MCS0402MC1002FE000, "RES SMD 10K OHM 1% 1/10W 0402", Device Package="0402 (1005 Metric)", Manufacturer="Vishay Beyschlag", Operating Temperature="-55°C ~ 175°C", Power (Watts)="0.1W, 1/10W", Ratings=AEC-Q200, Supplier Device Package=0402, Supplier Part Number 1=MCS0402-10.0K-MFCT-ND, Temperature Coefficient=±50ppm/°C, Tolerance=±1%
R10: library part MCS04020C1201FE000, "RES SMD 1.2K OHM 1% 1/10W 0402", Device Package="0402 (1005 Metric)", Manufacturer="Vishay Beyschlag", Operating Temperature="-55°C ~ 155°C", Power (Watts)="0.1W, 1/10W", Supplier Device Package=0402, Supplier Part Number 1=749-MCS04020C1201FE000CT-ND, Temperature Coefficient=±50ppm/°C, Tolerance=±1%
R14: library part CRT0603-FY-47R0ELF, "RES SMD 47 OHM 1% 1/10W 0603", Device Package="0603 (1608 Metric)", Manufacturer="Bourns Inc.", Operating Temperature="-55°C ~ 155°C", Power (Watts)="0.1W, 1/10W", Supplier Device Package=0603, Supplier Part Number 1=118-CRT0603-FY-47R0ELFCT-ND, Temperature Coefficient=±25ppm/°C, Tolerance=±1%
R15: library part RG1608P-203-B-T5, "RES SMD 20K OHM 0.1% 1/10W 0603", Device Package="0603 (1608 Metric)", Manufacturer=Susumu, Operating Temperature="-55°C ~ 155°C", Power (Watts)="0.1W, 1/10W", Ratings=AEC-Q200, Supplier Device Package=0603, Supplier Part Number 1=RG16P20.0KBCT-ND, Temperature Coefficient=±25ppm/°C, Tolerance=±0.1%
R16: library part CR0603AJ/-000ELF, "RES 0 OHM JUMPER 1/10W 0603", Device Package="0603 (1608 Metric)", Manufacturer="Bourns Inc.", Operating Temperature="-55°C ~ 155°C", Power (Watts)="0.1W, 1/10W", Ratings=AEC-Q200, Supplier Device Package=0603, Supplier Part Number 1=118-CR0603AJ/-000ELFCT-ND, Tolerance=Jumper
R19: library part ERJ-2RKF5232X, "RES SMD 52.3K OHM 1% 1/10W 0402", Device Package="0402 (1005 Metric)", Manufacturer="Panasonic Electronic Components", Operating Temperature="-55°C ~ 155°C", Power (Watts)="0.1W, 1/10W", Ratings=AEC-Q200, Supplier Device Package=0402, Supplier Part Number 1=P52.3KLCT-ND, Temperature Coefficient=±100ppm/°C, Tolerance=±1%
R20: library part RP73PF1E100KBTD, "RES 100K OHM 0.1% 1/10W 0402", Device Package="0402 (1005 Metric)", Manufacturer="TE Connectivity Passive Product", Operating Temperature="-55°C ~ 155°C", Power (Watts)="0.1W, 1/10W", Supplier Device Package=0402, Supplier Part Number 1=A127511CT-ND, Temperature Coefficient=±25ppm/°C, Tolerance=±0.1%
R21: library part MCS0402MC1001FE000, "RES SMD 1K OHM 1% 1/10W 0402", Device Package="0402 (1005 Metric)", Manufacturer="Vishay Beyschlag", Operating Temperature="-55°C ~ 175°C", Power (Watts)="0.1W, 1/10W", Ratings=AEC-Q200, Supplier Device Package=0402, Supplier Part Number 1=MCS0402-1.00K-MFCT-ND, Temperature Coefficient=±50ppm/°C, Tolerance=±1%
R25: library part ERJ-2RKF1201X, "RES SMD 1.2K OHM 1% 1/10W 0402", Device Package="0402 (1005 Metric)", Manufacturer="Panasonic Electronic Components", Operating Temperature="-55°C ~ 155°C", Power (Watts)="0.1W, 1/10W", Ratings=AEC-Q200, Supplier Device Package=0402, Supplier Part Number 1=P1.20KLCT-ND, Temperature Coefficient=±100ppm/°C, Tolerance=±1%
R26: library part RK73H1ERTTP1001F, "RES 1K OHM 1% 1/10W 0402", Device Package="0402 (1005 Metric)", Manufacturer="KOA Speer Electronics, Inc.", Operating Temperature="-55°C ~ 155°C", Power (Watts)="0.1W, 1/10W", Ratings=AEC-Q200, Supplier Device Package=0402, Supplier Part Number 1=2019-RK73H1ERTTP1001FCT-ND, Temperature Coefficient=±100ppm/°C, Tolerance=±1%
R27: library part RK73H1ETTP1100F, "RES 110 OHM 1% 1/10W 0402", Device Package="0402 (1005 Metric)", Manufacturer="KOA Speer Electronics, Inc.", Operating Temperature="-55°C ~ 155°C", Power (Watts)="0.1W, 1/10W", Ratings=AEC-Q200, Supplier Device Package=0402, Supplier Part Number 1=2019-RK73H1ETTP1100FCT-ND, Temperature Coefficient=±100ppm/°C, Tolerance=±1%
R28 R29: library part RK73G1ETTP1001D, "RES 1K OHM 0.5% 1/10W 0402", Device Package="0402 (1005 Metric)", Manufacturer="KOA Speer Electronics, Inc.", Operating Temperature="-55°C ~ 155°C", Power (Watts)="0.1W, 1/10W", Ratings=AEC-Q200, Supplier Device Package=0402, Supplier Part Number 1=2019-RK73G1ETTP1001DCT-ND, Temperature Coefficient=±50ppm/°C, Tolerance=±0.5%
R30: library part CRCW04021K00FKTD, "RES SMD 1K OHM 1% 1/16W 0402", Device Package="0402 (1005 Metric)", Manufacturer="Vishay Dale", Operating Temperature="-55°C ~ 155°C", Power (Watts)="0.063W, 1/16W", Ratings=AEC-Q200, Supplier Device Package=0402, Supplier Part Number 1=541-2957-1-ND, Temperature Coefficient=±100ppm/°C, Tolerance=±1%
R31: library part ERJ-U02F1100X, "RES 110 OHM 1% 1/10W 0402 SMD", Device Package="0402 (1005 Metric)", Manufacturer="Panasonic Electronic Components", Operating Temperature="-55°C ~ 155°C", Power (Watts)="0.1W, 1/10W", Ratings=AEC-Q200, Supplier Device Package=0402, Supplier Part Number 1=10-ERJ-U02F1100XCT-ND, Temperature Coefficient=±200ppm/°C, Tolerance=±1%
R32 R33: library part TNPW04021K00BYEP, "RES 1K OHM 0.1% 1/16W 0402", Device Package="0402 (1005 Metric)", Manufacturer="Vishay Dale", Operating Temperature="-55°C ~ 155°C", Power (Watts)="0.063W, 1/16W", Ratings=AEC-Q200, Supplier Device Package=0402, Supplier Part Number 1=541-4425-1-ND, Temperature Coefficient=±10ppm/°C, Tolerance=±0.1%
R36: library part RMEF0402FT1K00, "RES 1K OHM 1% 1/16W 0402", Device Package="0402 (1005 Metric)", Manufacturer="Stackpole Electronics Inc", Operating Temperature="-55°C ~ 155°C", Power (Watts)="0.063W, 1/16W", Ratings="7C1 RoHS w/out Exemption (100% Pb-Free), AEC-Q200", Supplier Device Package=0402, Supplier Part Number 1=738-RMEF0402FT1K00CT-ND, Temperature Coefficient=±100ppm/°C, Tolerance=±1%
SW1: "WS-TATU THT Tact Switch 6x6mm Right Angled Type with ground terminal, SPST-NO, 12VDC, 50mA, 160g", Manufacturer="Wurth Elektronik", Operating Temperature Max=85°C, Operating Temperature Min=-40°C, Rated Current=50mA, Rated Voltage=12VDC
